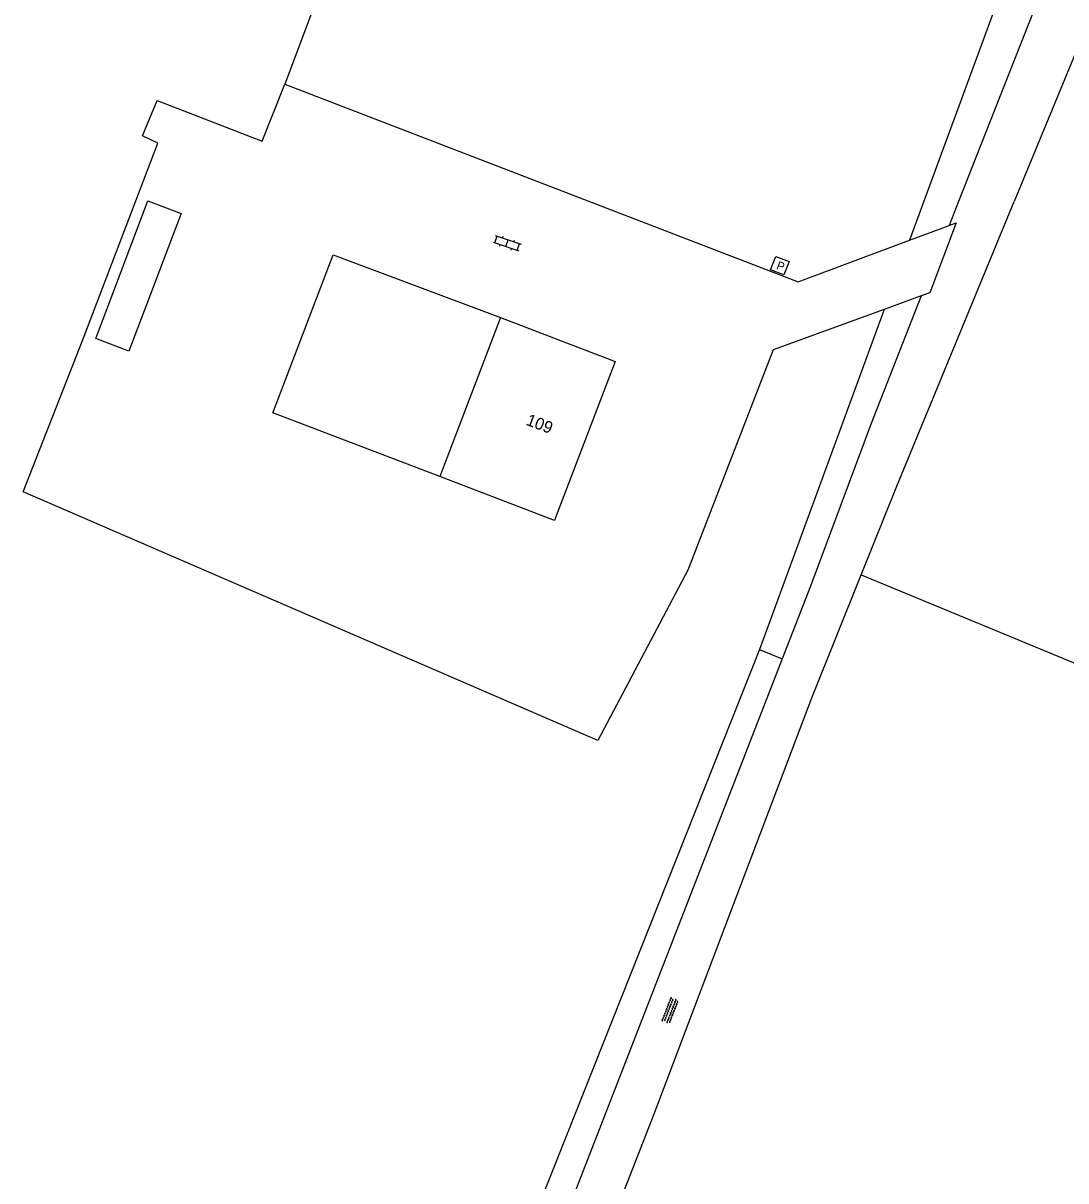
# Model space of a CAD drawing. Extents: x 130998 to 133001, y 398999 to 403002.
# Drawn here: x 131298.6 to 131386.2, y 400917.8 to 401015 of the extents above; entities that cross this region are included whole.
import ezdxf

# ---------------------------------------------------------------- set-up
doc = ezdxf.new("R2010")
doc.units = 0
for name, color, linetype in [('gg-anno-huisnummerreeks BGT', 7, 'Continuous'), ('gg-bbg-hoofdgebouw', 7, 'Continuous'), ('gg-bbg-luifel en loopbrug', 7, 'Continuous'), ('gg-bbg-open loods', 7, 'Continuous'), ('gg-knt-onverhard', 7, 'Continuous'), ('gg-knt-verharding', 7, 'Continuous'), ('gt-grn-groengrens', 7, 'Continuous'), ('gt-grn-vlakafsluiter', 7, 'Continuous'), ('gt-symb-brandput', 7, 'Continuous'), ('gt-symb-klinker verharding', 7, 'Continuous'), ('gt-symb-overige verharding', 7, 'Continuous')]:
    doc.layers.add(name, color=color, linetype=linetype)

# ---------------------------------------------------------------- blocks, each defined once
blk = doc.blocks.new('gt0-OVH')
at = {"layer": 'gt-symb-overige verharding'}
for points in [[(-0.972, 0.298), (-0.967, 0.308), (-0.965, 0.319), (-0.966, 0.33), (-0.971, 0.34), (-0.978, 0.348), (-0.988, 0.353), (-0.999, 0.355), (-1.01, 0.354), (-1.02, 0.349), (-1.028, 0.342), (-1.033, 0.332), (-1.035, 0.321), (-1.034, 0.31), (-1.029, 0.3), (-1.022, 0.292), (-1.012, 0.287), (-1.001, 0.285), (-0.99, 0.286), (-0.98, 0.291)], [(-0.872, 0.106), (-0.867, 0.116), (-0.865, 0.126), (-0.866, 0.137), (-0.871, 0.147), (-0.878, 0.156), (-0.888, 0.161), (-0.899, 0.163), (-0.91, 0.162), (-0.92, 0.157), (-0.928, 0.15), (-0.933, 0.14), (-0.935, 0.129), (-0.934, 0.118), (-0.929, 0.108), (-0.922, 0.1), (-0.912, 0.095), (-0.901, 0.092), (-0.89, 0.094), (-0.88, 0.098)], [(-0.772, 0.298), (-0.767, 0.308), (-0.765, 0.319), (-0.766, 0.33), (-0.771, 0.34), (-0.778, 0.348), (-0.788, 0.353), (-0.799, 0.355), (-0.81, 0.354), (-0.82, 0.349), (-0.828, 0.342), (-0.833, 0.332), (-0.835, 0.321), (-0.834, 0.31), (-0.829, 0.3), (-0.822, 0.292), (-0.812, 0.287), (-0.801, 0.285), (-0.79, 0.286), (-0.78, 0.291)], [(-0.672, 0.106), (-0.667, 0.116), (-0.665, 0.126), (-0.666, 0.137), (-0.671, 0.147), (-0.678, 0.156), (-0.688, 0.161), (-0.699, 0.163), (-0.71, 0.162), (-0.72, 0.157), (-0.728, 0.15), (-0.733, 0.14), (-0.735, 0.129), (-0.734, 0.118), (-0.729, 0.108), (-0.722, 0.1), (-0.712, 0.095), (-0.701, 0.092), (-0.69, 0.094), (-0.68, 0.098)], [(-0.572, 0.298), (-0.567, 0.308), (-0.565, 0.319), (-0.566, 0.33), (-0.571, 0.34), (-0.578, 0.348), (-0.588, 0.353), (-0.599, 0.355), (-0.61, 0.354), (-0.62, 0.349), (-0.628, 0.342), (-0.633, 0.332), (-0.635, 0.321), (-0.634, 0.31), (-0.629, 0.3), (-0.622, 0.292), (-0.612, 0.287), (-0.601, 0.285), (-0.59, 0.286), (-0.58, 0.291)], [(-0.472, 0.106), (-0.467, 0.116), (-0.465, 0.126), (-0.466, 0.137), (-0.471, 0.147), (-0.478, 0.156), (-0.488, 0.161), (-0.499, 0.163), (-0.51, 0.162), (-0.52, 0.157), (-0.528, 0.15), (-0.533, 0.14), (-0.535, 0.129), (-0.534, 0.118), (-0.529, 0.108), (-0.522, 0.1), (-0.512, 0.095), (-0.501, 0.092), (-0.49, 0.094), (-0.48, 0.098)], [(-0.372, 0.298), (-0.367, 0.308), (-0.365, 0.319), (-0.366, 0.33), (-0.371, 0.34), (-0.378, 0.348), (-0.388, 0.353), (-0.399, 0.355), (-0.41, 0.354), (-0.42, 0.349), (-0.428, 0.342), (-0.433, 0.332), (-0.435, 0.321), (-0.434, 0.31), (-0.429, 0.3), (-0.422, 0.292), (-0.412, 0.287), (-0.401, 0.285), (-0.39, 0.286), (-0.38, 0.291)], [(-0.272, 0.106), (-0.267, 0.116), (-0.265, 0.126), (-0.266, 0.137), (-0.271, 0.147), (-0.278, 0.156), (-0.288, 0.161), (-0.299, 0.163), (-0.31, 0.162), (-0.32, 0.157), (-0.328, 0.15), (-0.333, 0.14), (-0.335, 0.129), (-0.334, 0.118), (-0.329, 0.108), (-0.322, 0.1), (-0.312, 0.095), (-0.301, 0.092), (-0.29, 0.094), (-0.28, 0.098)], [(-0.172, 0.298), (-0.167, 0.308), (-0.165, 0.319), (-0.166, 0.33), (-0.171, 0.34), (-0.178, 0.348), (-0.188, 0.353), (-0.199, 0.355), (-0.21, 0.354), (-0.22, 0.349), (-0.228, 0.342), (-0.233, 0.332), (-0.235, 0.321), (-0.234, 0.31), (-0.229, 0.3), (-0.222, 0.292), (-0.212, 0.287), (-0.201, 0.285), (-0.19, 0.286), (-0.18, 0.291)], [(-0.072, 0.106), (-0.067, 0.116), (-0.065, 0.126), (-0.066, 0.137), (-0.071, 0.147), (-0.078, 0.156), (-0.088, 0.161), (-0.099, 0.163), (-0.11, 0.162), (-0.12, 0.157), (-0.128, 0.15), (-0.133, 0.14), (-0.135, 0.129), (-0.134, 0.118), (-0.129, 0.108), (-0.122, 0.1), (-0.112, 0.095), (-0.101, 0.092), (-0.09, 0.094), (-0.08, 0.098)], [(0.028, 0.298), (0.033, 0.308), (0.035, 0.319), (0.034, 0.33), (0.029, 0.34), (0.022, 0.348), (0.012, 0.353), (0.001, 0.355), (-0.01, 0.354), (-0.02, 0.349), (-0.028, 0.342), (-0.033, 0.332), (-0.035, 0.321), (-0.034, 0.31), (-0.029, 0.3), (-0.022, 0.292), (-0.012, 0.287), (-0.001, 0.285), (0.01, 0.286), (0.02, 0.291)], [(0.128, 0.106), (0.133, 0.116), (0.135, 0.126), (0.134, 0.137), (0.129, 0.147), (0.122, 0.156), (0.112, 0.161), (0.101, 0.163), (0.09, 0.162), (0.08, 0.157), (0.072, 0.15), (0.067, 0.14), (0.065, 0.129), (0.066, 0.118), (0.071, 0.108), (0.078, 0.1), (0.088, 0.095), (0.099, 0.092), (0.11, 0.094), (0.12, 0.098)], [(0.228, 0.298), (0.233, 0.308), (0.235, 0.319), (0.234, 0.33), (0.229, 0.34), (0.222, 0.348), (0.212, 0.353), (0.201, 0.355), (0.19, 0.354), (0.18, 0.349), (0.172, 0.342), (0.167, 0.332), (0.165, 0.321), (0.166, 0.31), (0.171, 0.3), (0.178, 0.292), (0.188, 0.287), (0.199, 0.285), (0.21, 0.286), (0.22, 0.291)], [(0.328, 0.106), (0.333, 0.116), (0.335, 0.126), (0.334, 0.137), (0.329, 0.147), (0.322, 0.156), (0.312, 0.161), (0.301, 0.163), (0.29, 0.162), (0.28, 0.157), (0.272, 0.15), (0.267, 0.14), (0.265, 0.129), (0.266, 0.118), (0.271, 0.108), (0.278, 0.1), (0.288, 0.095), (0.299, 0.092), (0.31, 0.094), (0.32, 0.098)], [(0.428, 0.298), (0.433, 0.308), (0.435, 0.319), (0.434, 0.33), (0.429, 0.34), (0.422, 0.348), (0.412, 0.353), (0.401, 0.355), (0.39, 0.354), (0.38, 0.349), (0.372, 0.342), (0.367, 0.332), (0.365, 0.321), (0.366, 0.31), (0.371, 0.3), (0.378, 0.292), (0.388, 0.287), (0.399, 0.285), (0.41, 0.286), (0.42, 0.291)], [(0.528, 0.106), (0.533, 0.116), (0.535, 0.126), (0.534, 0.137), (0.529, 0.147), (0.522, 0.156), (0.512, 0.161), (0.501, 0.163), (0.49, 0.162), (0.48, 0.157), (0.472, 0.15), (0.467, 0.14), (0.465, 0.129), (0.466, 0.118), (0.471, 0.108), (0.478, 0.1), (0.488, 0.095), (0.499, 0.092), (0.51, 0.094), (0.52, 0.098)], [(0.628, 0.298), (0.633, 0.308), (0.635, 0.319), (0.634, 0.33), (0.629, 0.34), (0.622, 0.348), (0.612, 0.353), (0.601, 0.355), (0.59, 0.354), (0.58, 0.349), (0.572, 0.342), (0.567, 0.332), (0.565, 0.321), (0.566, 0.31), (0.571, 0.3), (0.578, 0.292), (0.588, 0.287), (0.599, 0.285), (0.61, 0.286), (0.62, 0.291)], [(0.728, 0.106), (0.733, 0.116), (0.735, 0.126), (0.734, 0.137), (0.729, 0.147), (0.722, 0.156), (0.712, 0.161), (0.701, 0.163), (0.69, 0.162), (0.68, 0.157), (0.672, 0.15), (0.667, 0.14), (0.665, 0.129), (0.666, 0.118), (0.671, 0.108), (0.678, 0.1), (0.688, 0.095), (0.699, 0.092), (0.71, 0.094), (0.72, 0.098)], [(0.828, 0.298), (0.833, 0.308), (0.835, 0.319), (0.834, 0.33), (0.829, 0.34), (0.822, 0.348), (0.812, 0.353), (0.801, 0.355), (0.79, 0.354), (0.78, 0.349), (0.772, 0.342), (0.767, 0.332), (0.765, 0.321), (0.766, 0.31), (0.771, 0.3), (0.778, 0.292), (0.788, 0.287), (0.799, 0.285), (0.81, 0.286), (0.82, 0.291)], [(0.928, 0.106), (0.933, 0.116), (0.935, 0.126), (0.934, 0.137), (0.929, 0.147), (0.922, 0.156), (0.912, 0.161), (0.901, 0.163), (0.89, 0.162), (0.88, 0.157), (0.872, 0.15), (0.867, 0.14), (0.865, 0.129), (0.866, 0.118), (0.871, 0.108), (0.878, 0.1), (0.888, 0.095), (0.899, 0.092), (0.91, 0.094), (0.92, 0.098)], [(1.028, 0.298), (1.033, 0.308), (1.035, 0.319), (1.034, 0.33), (1.029, 0.34), (1.022, 0.348), (1.012, 0.353), (1.001, 0.355), (0.99, 0.354), (0.98, 0.349), (0.972, 0.342), (0.967, 0.332), (0.965, 0.321), (0.966, 0.31), (0.971, 0.3), (0.978, 0.292), (0.988, 0.287), (0.999, 0.285), (1.01, 0.286), (1.02, 0.291)], [(-0.972, -0.142), (-0.967, -0.132), (-0.965, -0.121), (-0.966, -0.11), (-0.971, -0.1), (-0.978, -0.092), (-0.988, -0.087), (-0.999, -0.085), (-1.01, -0.086), (-1.02, -0.091), (-1.028, -0.098), (-1.033, -0.108), (-1.035, -0.119), (-1.034, -0.13), (-1.029, -0.14), (-1.022, -0.148), (-1.012, -0.153), (-1.001, -0.155), (-0.99, -0.154), (-0.98, -0.149)], [(-0.872, -0.334), (-0.867, -0.324), (-0.865, -0.314), (-0.866, -0.303), (-0.871, -0.293), (-0.878, -0.284), (-0.888, -0.279), (-0.899, -0.277), (-0.91, -0.278), (-0.92, -0.283), (-0.928, -0.29), (-0.933, -0.3), (-0.935, -0.311), (-0.934, -0.322), (-0.929, -0.332), (-0.922, -0.34), (-0.912, -0.345), (-0.901, -0.348), (-0.89, -0.346), (-0.88, -0.342)], [(-0.772, -0.142), (-0.767, -0.132), (-0.765, -0.121), (-0.766, -0.11), (-0.771, -0.1), (-0.778, -0.092), (-0.788, -0.087), (-0.799, -0.085), (-0.81, -0.086), (-0.82, -0.091), (-0.828, -0.098), (-0.833, -0.108), (-0.835, -0.119), (-0.834, -0.13), (-0.829, -0.14), (-0.822, -0.148), (-0.812, -0.153), (-0.801, -0.155), (-0.79, -0.154), (-0.78, -0.149)], [(-0.672, -0.334), (-0.667, -0.324), (-0.665, -0.314), (-0.666, -0.303), (-0.671, -0.293), (-0.678, -0.284), (-0.688, -0.279), (-0.699, -0.277), (-0.71, -0.278), (-0.72, -0.283), (-0.728, -0.29), (-0.733, -0.3), (-0.735, -0.311), (-0.734, -0.322), (-0.729, -0.332), (-0.722, -0.34), (-0.712, -0.345), (-0.701, -0.348), (-0.69, -0.346), (-0.68, -0.342)], [(-0.572, -0.142), (-0.567, -0.132), (-0.565, -0.121), (-0.566, -0.11), (-0.571, -0.1), (-0.578, -0.092), (-0.588, -0.087), (-0.599, -0.085), (-0.61, -0.086), (-0.62, -0.091), (-0.628, -0.098), (-0.633, -0.108), (-0.635, -0.119), (-0.634, -0.13), (-0.629, -0.14), (-0.622, -0.148), (-0.612, -0.153), (-0.601, -0.155), (-0.59, -0.154), (-0.58, -0.149)], [(-0.472, -0.334), (-0.467, -0.324), (-0.465, -0.314), (-0.466, -0.303), (-0.471, -0.293), (-0.478, -0.284), (-0.488, -0.279), (-0.499, -0.277), (-0.51, -0.278), (-0.52, -0.283), (-0.528, -0.29), (-0.533, -0.3), (-0.535, -0.311), (-0.534, -0.322), (-0.529, -0.332), (-0.522, -0.34), (-0.512, -0.345), (-0.501, -0.348), (-0.49, -0.346), (-0.48, -0.342)], [(-0.372, -0.142), (-0.367, -0.132), (-0.365, -0.121), (-0.366, -0.11), (-0.371, -0.1), (-0.378, -0.092), (-0.388, -0.087), (-0.399, -0.085), (-0.41, -0.086), (-0.42, -0.091), (-0.428, -0.098), (-0.433, -0.108), (-0.435, -0.119), (-0.434, -0.13), (-0.429, -0.14), (-0.422, -0.148), (-0.412, -0.153), (-0.401, -0.155), (-0.39, -0.154), (-0.38, -0.149)], [(-0.272, -0.334), (-0.267, -0.324), (-0.265, -0.314), (-0.266, -0.303), (-0.271, -0.293), (-0.278, -0.284), (-0.288, -0.279), (-0.299, -0.277), (-0.31, -0.278), (-0.32, -0.283), (-0.328, -0.29), (-0.333, -0.3), (-0.335, -0.311), (-0.334, -0.322), (-0.329, -0.332), (-0.322, -0.34), (-0.312, -0.345), (-0.301, -0.348), (-0.29, -0.346), (-0.28, -0.342)], [(-0.172, -0.142), (-0.167, -0.132), (-0.165, -0.121), (-0.166, -0.11), (-0.171, -0.1), (-0.178, -0.092), (-0.188, -0.087), (-0.199, -0.085), (-0.21, -0.086), (-0.22, -0.091), (-0.228, -0.098), (-0.233, -0.108), (-0.235, -0.119), (-0.234, -0.13), (-0.229, -0.14), (-0.222, -0.148), (-0.212, -0.153), (-0.201, -0.155), (-0.19, -0.154), (-0.18, -0.149)], [(-0.072, -0.334), (-0.067, -0.324), (-0.065, -0.314), (-0.066, -0.303), (-0.071, -0.293), (-0.078, -0.284), (-0.088, -0.279), (-0.099, -0.277), (-0.11, -0.278), (-0.12, -0.283), (-0.128, -0.29), (-0.133, -0.3), (-0.135, -0.311), (-0.134, -0.322), (-0.129, -0.332), (-0.122, -0.34), (-0.112, -0.345), (-0.101, -0.348), (-0.09, -0.346), (-0.08, -0.342)], [(0.028, -0.142), (0.033, -0.132), (0.035, -0.121), (0.034, -0.11), (0.029, -0.1), (0.022, -0.092), (0.012, -0.087), (0.001, -0.085), (-0.01, -0.086), (-0.02, -0.091), (-0.028, -0.098), (-0.033, -0.108), (-0.035, -0.119), (-0.034, -0.13), (-0.029, -0.14), (-0.022, -0.148), (-0.012, -0.153), (-0.001, -0.155), (0.01, -0.154), (0.02, -0.149)], [(0.128, -0.334), (0.133, -0.324), (0.135, -0.314), (0.134, -0.303), (0.129, -0.293), (0.122, -0.284), (0.112, -0.279), (0.101, -0.277), (0.09, -0.278), (0.08, -0.283), (0.072, -0.29), (0.067, -0.3), (0.065, -0.311), (0.066, -0.322), (0.071, -0.332), (0.078, -0.34), (0.088, -0.345), (0.099, -0.348), (0.11, -0.346), (0.12, -0.342)], [(0.228, -0.142), (0.233, -0.132), (0.235, -0.121), (0.234, -0.11), (0.229, -0.1), (0.222, -0.092), (0.212, -0.087), (0.201, -0.085), (0.19, -0.086), (0.18, -0.091), (0.172, -0.098), (0.167, -0.108), (0.165, -0.119), (0.166, -0.13), (0.171, -0.14), (0.178, -0.148), (0.188, -0.153), (0.199, -0.155), (0.21, -0.154), (0.22, -0.149)], [(0.328, -0.334), (0.333, -0.324), (0.335, -0.314), (0.334, -0.303), (0.329, -0.293), (0.322, -0.284), (0.312, -0.279), (0.301, -0.277), (0.29, -0.278), (0.28, -0.283), (0.272, -0.29), (0.267, -0.3), (0.265, -0.311), (0.266, -0.322), (0.271, -0.332), (0.278, -0.34), (0.288, -0.345), (0.299, -0.348), (0.31, -0.346), (0.32, -0.342)], [(0.428, -0.142), (0.433, -0.132), (0.435, -0.121), (0.434, -0.11), (0.429, -0.1), (0.422, -0.092), (0.412, -0.087), (0.401, -0.085), (0.39, -0.086), (0.38, -0.091), (0.372, -0.098), (0.367, -0.108), (0.365, -0.119), (0.366, -0.13), (0.371, -0.14), (0.378, -0.148), (0.388, -0.153), (0.399, -0.155), (0.41, -0.154), (0.42, -0.149)], [(0.528, -0.334), (0.533, -0.324), (0.535, -0.314), (0.534, -0.303), (0.529, -0.293), (0.522, -0.284), (0.512, -0.279), (0.501, -0.277), (0.49, -0.278), (0.48, -0.283), (0.472, -0.29), (0.467, -0.3), (0.465, -0.311), (0.466, -0.322), (0.471, -0.332), (0.478, -0.34), (0.488, -0.345), (0.499, -0.348), (0.51, -0.346), (0.52, -0.342)], [(0.628, -0.142), (0.633, -0.132), (0.635, -0.121), (0.634, -0.11), (0.629, -0.1), (0.622, -0.092), (0.612, -0.087), (0.601, -0.085), (0.59, -0.086), (0.58, -0.091), (0.572, -0.098), (0.567, -0.108), (0.565, -0.119), (0.566, -0.13), (0.571, -0.14), (0.578, -0.148), (0.588, -0.153), (0.599, -0.155), (0.61, -0.154), (0.62, -0.149)], [(0.728, -0.334), (0.733, -0.324), (0.735, -0.314), (0.734, -0.303), (0.729, -0.293), (0.722, -0.284), (0.712, -0.279), (0.701, -0.277), (0.69, -0.278), (0.68, -0.283), (0.672, -0.29), (0.667, -0.3), (0.665, -0.311), (0.666, -0.322), (0.671, -0.332), (0.678, -0.34), (0.688, -0.345), (0.699, -0.348), (0.71, -0.346), (0.72, -0.342)], [(0.828, -0.142), (0.833, -0.132), (0.835, -0.121), (0.834, -0.11), (0.829, -0.1), (0.822, -0.092), (0.812, -0.087), (0.801, -0.085), (0.79, -0.086), (0.78, -0.091), (0.772, -0.098), (0.767, -0.108), (0.765, -0.119), (0.766, -0.13), (0.771, -0.14), (0.778, -0.148), (0.788, -0.153), (0.799, -0.155), (0.81, -0.154), (0.82, -0.149)], [(0.928, -0.334), (0.933, -0.324), (0.935, -0.314), (0.934, -0.303), (0.929, -0.293), (0.922, -0.284), (0.912, -0.279), (0.901, -0.277), (0.89, -0.278), (0.88, -0.283), (0.872, -0.29), (0.867, -0.3), (0.865, -0.311), (0.866, -0.322), (0.871, -0.332), (0.878, -0.34), (0.888, -0.345), (0.899, -0.348), (0.91, -0.346), (0.92, -0.342)], [(1.028, -0.142), (1.033, -0.132), (1.035, -0.121), (1.034, -0.11), (1.029, -0.1), (1.022, -0.092), (1.012, -0.087), (1.001, -0.085), (0.99, -0.086), (0.98, -0.091), (0.972, -0.098), (0.967, -0.108), (0.965, -0.119), (0.966, -0.13), (0.971, -0.14), (0.978, -0.148), (0.988, -0.153), (0.999, -0.155), (1.01, -0.154), (1.02, -0.149)]]:
    blk.add_lwpolyline(points, close=True, dxfattribs=at)
blk = doc.blocks.new('gt0-BPUT')
at = {"layer": 'gt-symb-brandput'}
blk.add_lwpolyline([(-0.599, -0.599), (-0.599, 0.601), (0.601, 0.601), (0.601, -0.599)], close=True, dxfattribs=at)
blk.add_text('P', height=0.7, dxfattribs=at).set_placement((-0.233, -0.35))
blk = doc.blocks.new('gt0-KL1')
at = {"layer": 'gt-symb-klinker verharding'}
for p, q in [((-1.15, 0.3), (1.15, 0.3)), ((-1, -0.3), (-1, 0.3)), ((-0.5, 0.3), (-0.5, 0.45)), ((0, -0.3), (0, 0.3)), ((0.5, 0.3), (0.5, 0.45)), ((1, -0.3), (1, 0.3)), ((-1.15, -0.3), (1.15, -0.3)), ((-0.5, -0.45), (-0.5, -0.3)), ((0.5, -0.45), (0.5, -0.3))]:
    blk.add_line(p, q, dxfattribs=at)

msp = doc.modelspace()

# ---------------------------------------------------------------- linework, layer by layer
at = {"layer": 'gg-bbg-hoofdgebouw'}
msp.add_line((131338.714, 400990.261), (131333.614, 400976.901), dxfattribs=at)
for points in [[(131338.714, 400990.261), (131348.348, 400986.572), (131343.309, 400973.376)], [(131343.309, 400973.376), (131343.247, 400973.212), (131333.614, 400976.901)]]:
    msp.add_lwpolyline(points, dxfattribs=at)
at = {"layer": 'gg-bbg-luifel en loopbrug'}
msp.add_lwpolyline([(131304.718, 400988.5), (131309.111, 401000.042), (131311.907, 400998.978), (131307.513, 400987.436), (131304.718, 400988.5)], dxfattribs=at)
at = {"layer": 'gg-bbg-open loods'}
for points in [[(131319.646, 400982.384), (131324.67, 400995.506), (131338.714, 400990.261)], [(131333.614, 400976.901), (131319.601, 400982.266), (131319.646, 400982.384)]]:
    msp.add_lwpolyline(points, dxfattribs=at)
at = {"layer": 'gg-knt-onverhard'}
for p, q in [((131387.37, 401013.351), (131381.864, 401000)), ((131380.624, 401008.731), (131377.189, 401000)), ((131377.189, 401000), (131376.394, 400997.984))]:
    msp.add_line(p, q, dxfattribs=at)
for points in [[(131385.041, 401019.947), (131384.655, 401018.978), (131380.624, 401008.731)], [(131369.022, 400968.66), (131372.001, 400976.098), (131381.864, 401000)], [(131374.063, 400992.07), (131369.846, 400981.371), (131364.754, 400967.705), (131362.381, 400961.605)], [(131348.455, 400915.108), (131348.935, 400916.523), (131351.626, 400923.393), (131364.883, 400958.327), (131369.022, 400968.66)], [(131362.381, 400961.605), (131337.933, 400898.753), (131335.771, 400892.212), (131322.357, 400858.484), (131326.465, 400856.84), (131327.757, 400860.068), (131329.888, 400860.733), (131331.874, 400865.697), (131330.743, 400867.835), (131341.825, 400895.562)]]:
    msp.add_lwpolyline(points, dxfattribs=at)
at = {"layer": 'gg-knt-verharding'}
for p, q in [((131373.084, 400996.747), (131376.394, 400997.984)), ((131374.063, 400992.07), (131370.952, 400990.935))]:
    msp.add_line(p, q, dxfattribs=at)
for points in [[(131309.873, 401008.487), (131318.703, 401005.064), (131320.603, 401009.851)], [(131320.603, 401009.851), (131363.728, 400993.249), (131373.084, 400996.747)], [(131298.626, 400975.631), (131303.677, 400988.463), (131309.934, 401004.901), (131308.65, 401005.508), (131309.873, 401008.487)], [(131376.394, 400997.984), (131376.982, 400998.204), (131374.769, 400992.327), (131374.063, 400992.07)], [(131370.952, 400990.935), (131361.628, 400987.535), (131354.454, 400969.037), (131346.882, 400954.754), (131298.626, 400975.631)]]:
    msp.add_lwpolyline(points, dxfattribs=at)
at = {"layer": 'gt-grn-groengrens'}
for p, q in [((131381.678, 401020.165), (131373.084, 400996.747)), ((131370.952, 400990.935), (131360.471, 400962.374)), ((131360.471, 400962.374), (131308.5, 400831.654)), ((131360.471, 400962.374), (131362.381, 400961.605))]:
    msp.add_line(p, q, dxfattribs=at)
msp.add_lwpolyline([(131369.022, 400968.66), (131438.741, 400939.824), (131455.066, 400978.568), (131447.85, 400981.366)], dxfattribs=at)
at = {"layer": 'gt-grn-vlakafsluiter'}
msp.add_lwpolyline([(131392.282, 401061.751), (131376.4, 401023.646), (131332.061, 401040.36), (131320.603, 401009.851)], dxfattribs=at)

# ---------------------------------------------------------------- block references
at = {"layer": 'gt-symb-brandput', "rotation": -20.882825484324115}
msp.add_blockref('gt0-BPUT', (131362.182, 400994.605), dxfattribs=at)
at = {"layer": 'gt-symb-klinker verharding', "rotation": -18.906060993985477}
msp.add_blockref('gt0-KL1', (131339.276, 400996.5), dxfattribs=at)
at = {"layer": 'gt-symb-overige verharding', "rotation": 68.64562263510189}
msp.add_blockref('gt0-OVH', (131352.972, 400932.072), dxfattribs=at)

# ---------------------------------------------------------------- texts
at = {"layer": 'gg-anno-huisnummerreeks BGT'}
msp.add_text('109', height=1, rotation=339.1, dxfattribs=at).set_placement((131340.794, 400981.268))

doc.saveas('drawing.dxf')
